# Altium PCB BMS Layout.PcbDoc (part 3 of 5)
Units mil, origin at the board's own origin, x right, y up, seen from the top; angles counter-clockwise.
Board outline 5576.78 x 4051.82 mil, 6 copper layers (Top Layer, GND1, Analog Signal, Power, GND2, Bottom Layer), stack 61.2 mil thick; 425 components, 206 nets, 1164 pads, 390 vias.
Unrouted connection lines stored in the file: 32.
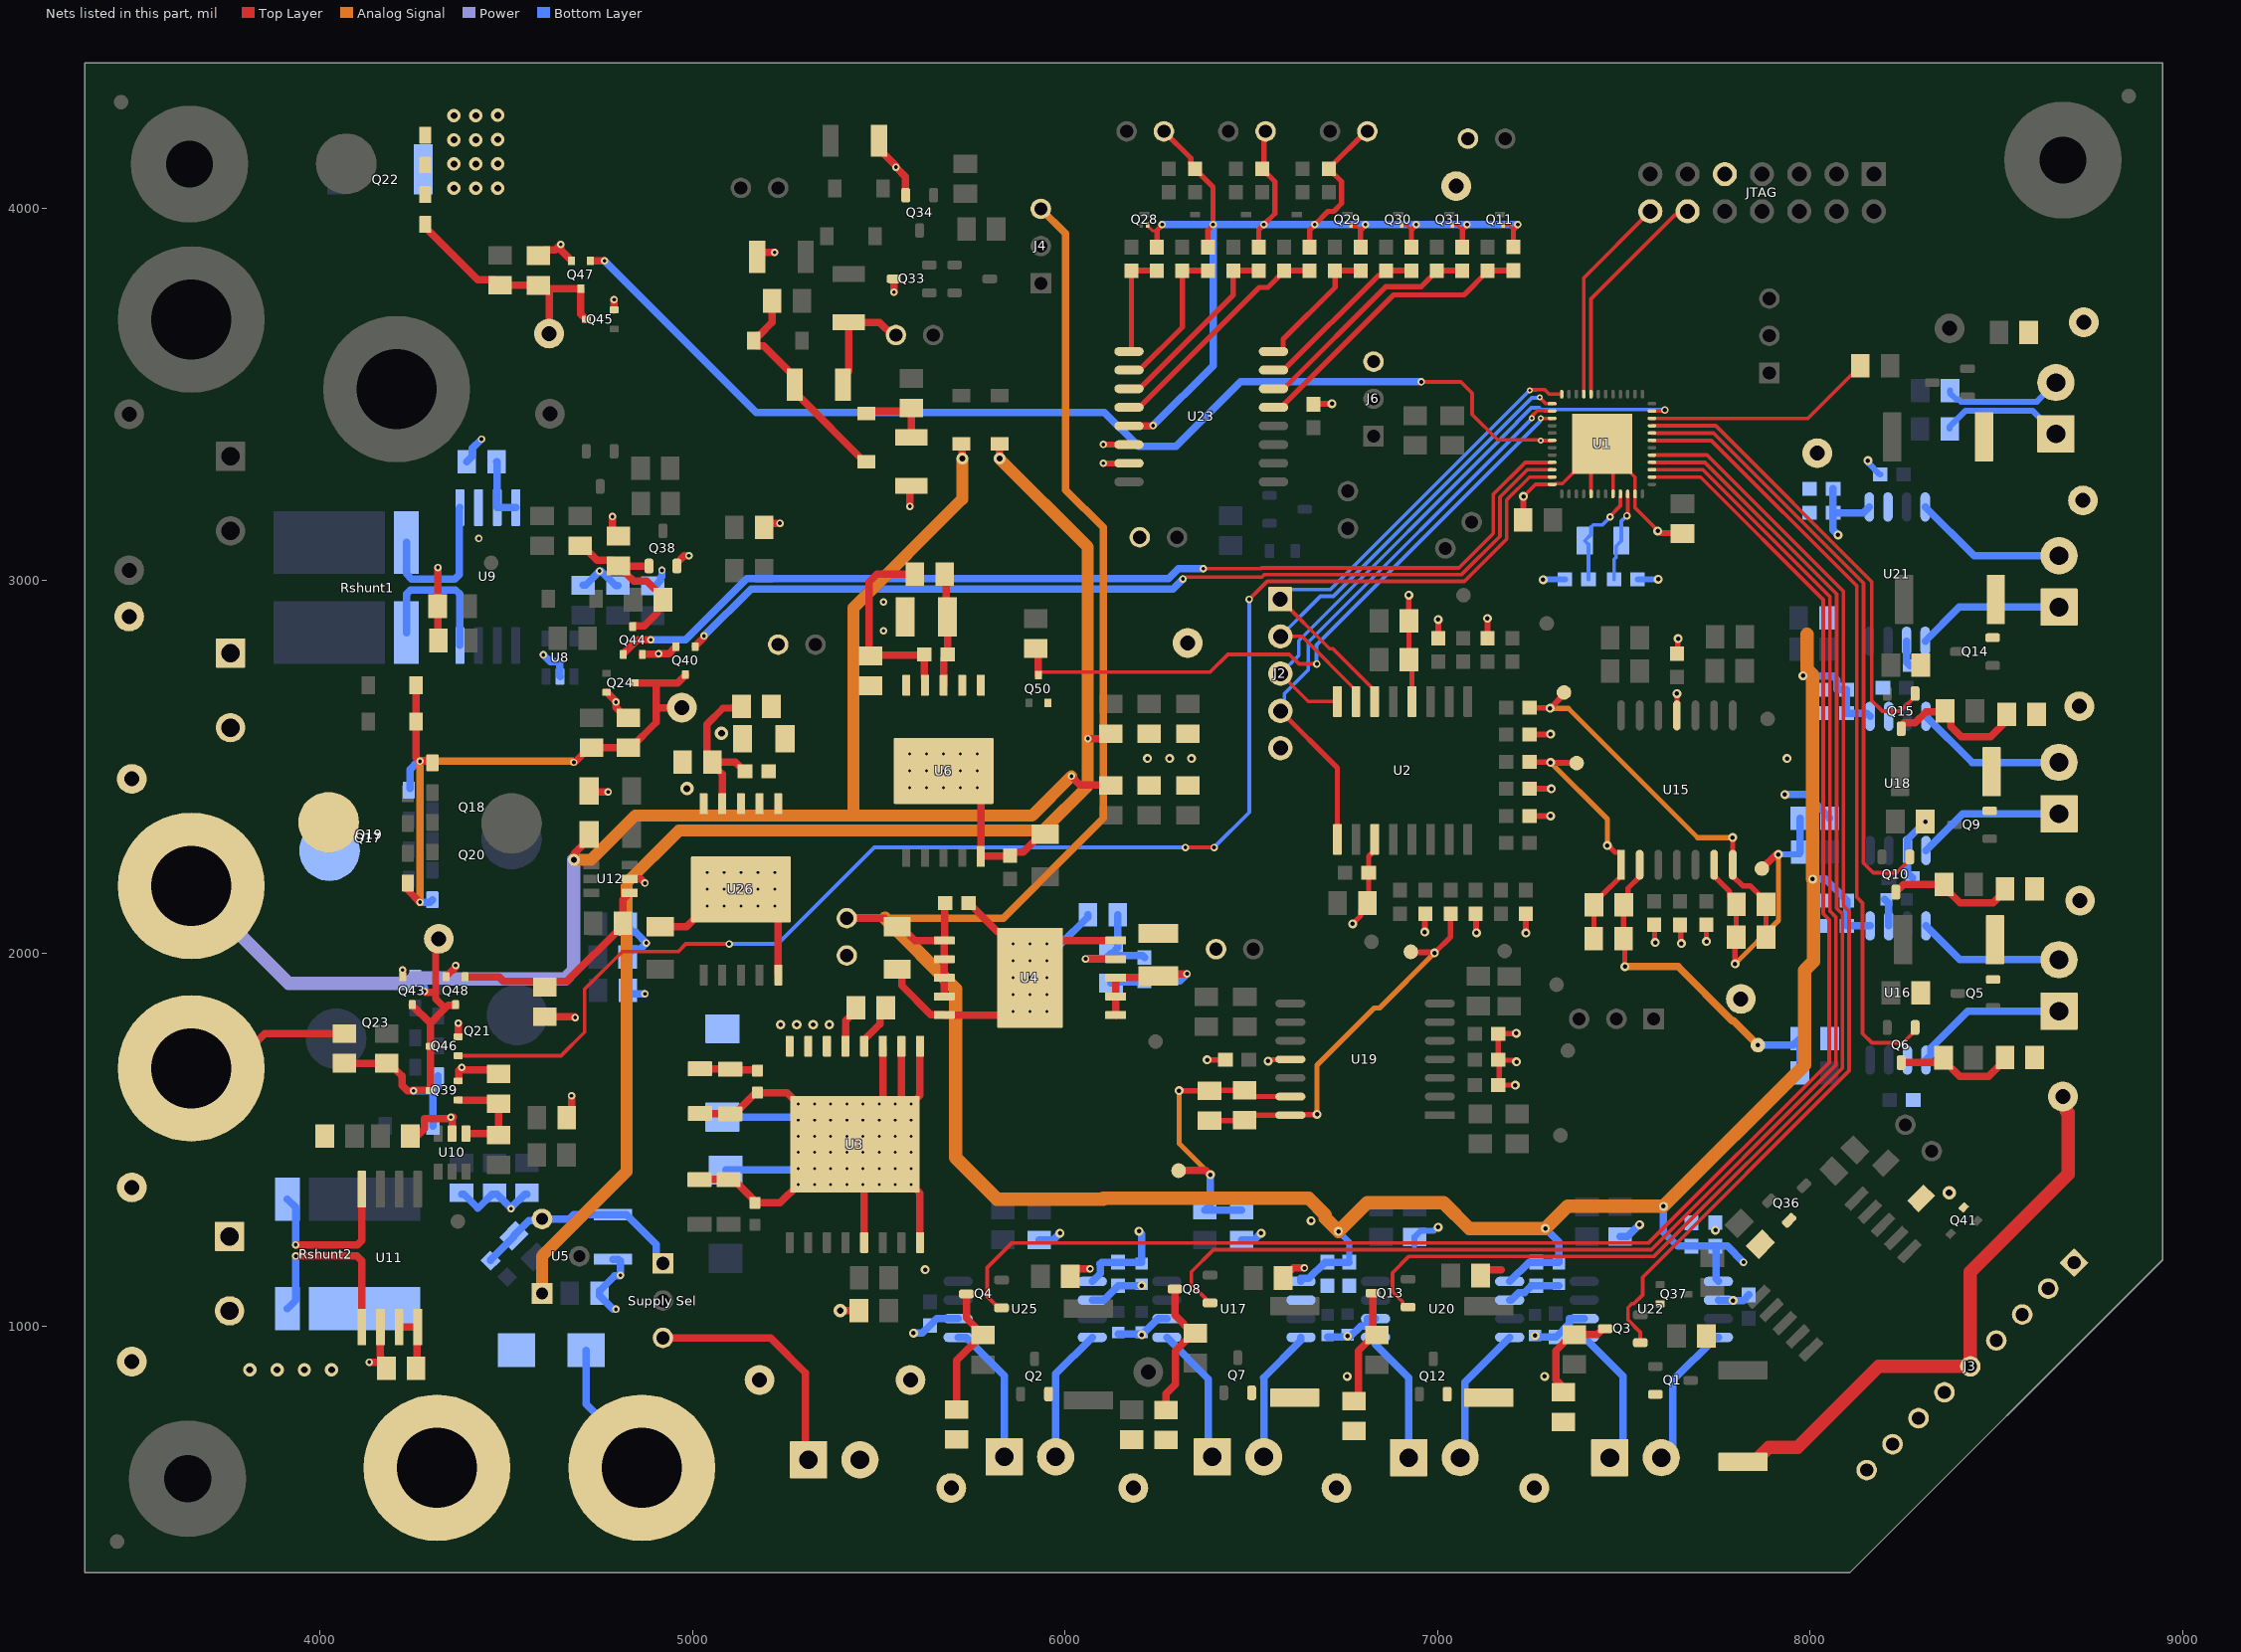
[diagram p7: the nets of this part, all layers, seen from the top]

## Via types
v1: diameter 20, hole 10, Top Layer to Bottom Layer, tented both sides, 113 vias
v2: diameter 24, hole 12, Top Layer to Bottom Layer, tented both sides, 103 vias
v3: diameter 19.68, hole 7.87, Top Layer to Bottom Layer, 93 vias
v4: diameter 36, hole 18, Top Layer to Bottom Layer, 46 vias
v5: diameter 36, hole 18, Top Layer to Bottom Layer, tented both sides, 12 vias
v6: diameter 16, hole 8, Top Layer to Bottom Layer, tented both sides, 10 vias
v7: diameter 26, hole 13, Top Layer to Bottom Layer, tented both sides, 7 vias
v8: diameter 32, hole 16, Top Layer to Bottom Layer, tented both sides, 3 vias
v9: diameter 28, hole 14, Top Layer to Bottom Layer, tented both sides, 2 vias
v10: diameter 20, hole 12, Top Layer to Bottom Layer, tented both sides, 1 vias

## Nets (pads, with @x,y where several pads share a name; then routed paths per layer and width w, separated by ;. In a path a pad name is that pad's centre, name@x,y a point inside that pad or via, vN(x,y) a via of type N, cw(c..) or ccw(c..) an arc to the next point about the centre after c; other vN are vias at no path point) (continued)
12Vcc: C16.1 C17.1 C87.2 C88.2 C90.2 C91.2 C95.2 C96.2 C99.2 C100.2 C104.2 C105.2 C109.2 C110.2 C153.2 C155.2 J4.3 J_LS.2 Q36.2 R139.2 U4.1 U4.2 U4.3 U4.4 U16.5 U17.5 U18.5 U20.5 U21.5 U22.5 U25.5 | length 9472.5
  Top Layer w20: J_LS.2@5414.11,2094.18 5515.48,2094.18 5538.48,2071.18 C16.1@5549.31,2071.18 5560.14,2071.18 5597.14,2034.18 U4.1@5675.81,2034.18 ; U4.4@5675.81,1884.18 U4.3@5675.81,1934.18 U4.2@5675.81,1984.18 U4.1@5675.81,2034.18 ; C17.1@5677.88,2134.77 5676.84,2133.73 5676.84,2035.01 5676.02,2034.18 U4.1@5675.81,2034.18
  Analog Signal w20: J_LS.2@5414.11,2094.18 5516.47,2094.18 5833.83,2094.18 6102.36,2362.71 6102.36,3142.77 6001.45,3243.68 6001.45,3931.74 J4.3@5935.04,3998.15
  Analog Signal w36: 5516.47,2094.18 5705.77,1904.88 5705.77,1451.83 5817.15,1340.44 6102.36,1340.44 ; 6102.36,1342.24 6653.77,1342.24 6698.5,1297.51 6698.5,1288.89 v2(6733.82,1253.57) 6811.35,1331.1 7015.12,1331.1 7085.04,1261.18 v2(7288.82,1261.18) 7348.76,1321.12 v2(7606.04,1321.12) 7984.64,1699.72 7984.64,1954.47 8008.54,1978.37 8008.54,2196.73 v2(8006.44,2198.83) 8006.44,2747.44 7991.01,2762.87 7991.01,2856.69
  Bottom Layer w16: v2(6733.82,1253.57) 6762.5,1224.88 C90.2@6762.5,1170.85
  Bottom Layer w20: U25.5@6073.05,1119.19 6095.26,1141.4 6095.26,1164.66 6093.68,1166.24 6098.29,1170.85 C153.2@6142.52,1170.85 6205.76,1170.85 6205.76,1246.96 v2(6198.39,1254.32) ; U17.5@6633.19,1119.19 6633.19,1127.26 6654.15,1127.26 6697.74,1170.85 C91.2@6704.63,1170.85 C90.2@6762.5,1170.85 ; U20.5@7193.33,1119.19 7244.8,1170.66 C100.2@7264.56,1170.66 7325.17,1170.66 7325.36,1170.85 7325.36,1224.64 v2(7288.82,1261.18) ; v2(7606.04,1321.12) 7606.04,1251.57 7643.86,1213.74 C110.2@7681.16,1213.74 7745.28,1213.74 C109.2@7745.47,1213.93 7778.06,1213.93 v1(7821.14,1170.85) ; C109.2@7746.92,1200.38 7746.92,1125.75 U22.5@7753.47,1119.19 ; v2(7980.3,2745.3) 7981.11,2744.49 8061.59,2744.49 8072.14,2733.95 8072.14,2708.64 8097.45,2708.64 C96.2@8097.45,2707.79 C95.2@8097.45,2644.58 8152.14,2644.58 U18.5@8160.57,2636.14 ; v2(8006.44,2198.83) 8041.27,2198.83 8097.92,2142.18 C88.2@8097.92,2141.33 8097.92,2073.83 8098.18,2073.57 U16.5@8160.57,2073.57 ; C105.2@8061.41,3247.28 C104.2@8061.41,3182.18 ; v2(8074.57,3123.03) 8061.41,3136.19 C104.2@8061.41,3182.18 ; U21.5@8158.53,3198 8142.71,3182.18 C104.2@8061.41,3182.18
A1_RX: JTAG.14 U1.21 | length 558
  Top Layer w10: U1.21@7391.9,3507.52 7391.9,3812.86 JTAG.14@7570.58,3991.54
A1_TX: JTAG.12 U1.20 | length 612.4
  Top Layer w10: U1.20@7411.59,3500.71 7411.59,3532.02 7411.5,3532.11 7411.5,3756.81 7635.72,3981.02 7660.06,3981.02 JTAG.12@7670.58,3991.54
ADC_CS: J2.4 U1.26 U2.1 | length 1539.8
  Top Layer w10: v6(7252.8,3436.03) 7253.95,3437.18 7253.95,3442.59 7268.1,3456.75 7285.5,3456.75 7286.54,3455.71 7306.98,3455.71 U1.26@7307.26,3455.43
  Top Layer w14: J2.4@6577.98,2650.6 6730.9,2497.69 U2.1@6730.9,2305.8
  Bottom Layer w10: J2.4@6577.98,2650.6 6588.5,2661.12 6588.5,2696.8 6652.71,2761.01 6652.71,2834.96 7252.8,3435.06 v6(7252.8,3436.03)
ADC_DIN: J2.1 U1.24 U2.14 | length 1378.9
  Top Layer w10: J2.1@6576.98,2950.6 6709.92,2817.67 6718.64,2817.67 6830.9,2705.41 U2.14@6830.9,2675.88 ; v6(7246.73,3510.92) 7247.87,3512.06 7264.35,3512.06 7265.09,3512.8 7287.38,3512.8 7299.47,3500.71 U1.24@7332.85,3500.71
  Bottom Layer w10: J2.1@6576.98,2950.6 6602.52,2976.14 6712.27,2976.14 7246.73,3510.59 v6(7246.73,3510.92)
ADC_DOUT: J2.2 U1.25 U2.15 | length 1294.4
  Top Layer w10: J2.2@6577.98,2850.6 6635.7,2850.6 6780.9,2705.41 U2.15@6780.9,2675.88 ; v6(7273.79,3491.8) 7290.2,3475.39 7306.98,3475.39 U1.25@7307.26,3475.12
  Bottom Layer w10: J2.2@6577.98,2850.6 6685.52,2958.14 6719.73,2958.14 7252.25,3490.66 7272.64,3490.66 v6(7273.79,3491.8)
ADC_SCLK: J2.3 U1.11 U2.16 | length 1573.4
  Top Layer w10: J2.3@6577.98,2750.6 6652.71,2675.88 U2.16@6730.9,2675.88 ; U1.11@7574.97,3455.43 7603.83,3455.43 7607.14,3458.75 v10(7609.85,3458.75)
  Bottom Layer w10: J2.3@6577.98,2750.6 6627.2,2799.82 6627.2,2838.9 7212.37,3424.07 7212.37,3425.29 7251.18,3464.11 7272.63,3464.11 7277.49,3459.25 7582.93,3459.25 7583.44,3458.75 v10(7609.85,3458.75)
BAL1_MCU: R75.2 U1.10 | length 618.2
  Top Layer w10: U1.10@7574.97,3435.75 7993.19,3435.75 R75.2@8134.59,3577.15
BAL2_MCU: Q15.1 U1.9 | length 1234.9
  Top Layer w10: U1.9@7574.97,3416.06 7746.15,3416.06 8164.96,2997.25 8164.96,2678.26 8193.42,2649.8 8242.05,2649.8 8281.42,2689.16 Q15.1@8281.42,2697.03
BAL3_MCU: Q10.1 U1.8 | length 1643.3
  Top Layer w10: U1.8@7574.97,3396.38 7740.38,3396.38 8142.89,2993.87 8142.89,2601.96 8142.7,2601.77 8142.7,2569.66 8142.89,2569.48 8142.89,2242.08 8168.77,2216.19 8231.96,2216.19 8266.97,2251.2 Q10.1@8266.97,2258.58
BAL4_MCU: Q6.1 U1.7 | length 2093.6
  Top Layer w10: U1.7@7574.97,3376.69 7575.25,3376.41 7734.88,3376.41 8124.7,2986.59 8124.7,2150.41 8140.57,2134.54 8140.57,1784.45 8165.55,1759.46 8249.02,1759.46 8274.61,1785.05 8274.61,1785.61 8281.42,1792.42 Q6.1@8281.42,1800.78
BAL5_MCU: Q3.1 U1.5 | length 2951.1
  Top Layer w10: Q3.1@7543.79,954.71 7543.79,983.09 7511.11,1015.78 7511.11,1049.11 7521.32,1059.32 7526.44,1059.32 7550.17,1083.04 7550.17,1130.4 8104.57,1684.8 8104.57,2112.52 8088.7,2128.38 8088.7,2971.68 7723.07,3337.32 U1.5@7574.97,3337.32
BAL6_MCU: Q13.1 U1.4 | length 3469.6
  Top Layer w10: Q13.1@6920.58,1050.29 6913.2,1050.29 6906.45,1057.03 6906.45,1064.42 6879.07,1091.8 6879.07,1142.4 6923.31,1186.65 7580.96,1186.65 8086.57,1692.26 8086.57,2105.06 8070.7,2120.93 8070.7,2964.23 7717.29,3317.64 U1.4@7574.97,3317.64
BAL7_MCU: Q8.1 U1.3 | length 3946.5
  Top Layer w10: Q8.1@6389.05,1061.45 6338.86,1111.63 6338.86,1144.98 6398.53,1204.65 7573.5,1204.65 8068.57,1699.71 8068.57,2097.61 8052.7,2113.47 8052.7,2956.77 7711.52,3297.95 U1.3@7574.97,3297.95
BAL8_MCU: Q4.1 U1.2 | length 4460.7
  Top Layer w10: Q4.1@5829.51,1048.31 5821.63,1048.31 5791.21,1078.73 5791.21,1156.35 5857.5,1222.65 7566.05,1222.65 8050.57,1707.17 8050.57,2090.15 8034.7,2106.01 8034.7,2949.31 7705.75,3278.27 U1.2@7574.97,3278.27
Batt1_4V2: Batt_1.1 Batt_2.2 J3.2 R40.1 R43.2 R106.1 TP39.1 U21.8 | length 748.8
  Bottom Layer w16: R106.1@8374.23,3407.51 8374.23,3414.01 8417.04,3456.82 8596.45,3456.82 Batt_1.1@8659.37,3393.9
  Bottom Layer w20: U21.8@8308.53,3198 8439.43,3067.11 Batt_2.2@8667.67,3067.11
Batt2_8V4: Batt_2.1 Batt_3.2 J3.3 Q14.2 R36.1 R37.1 TP38.1 U18.8 U21.1 | length 811
  Bottom Layer w20: U21.1@8308.53,2837.77 8399.87,2929.11 Batt_2.1@8667.67,2929.11 ; U18.8@8310.57,2636.14 8434.25,2512.46 Batt_3.2@8673.38,2512.46
Batt3_12V6: Batt_3.1 Batt_4.2 J3.4 Q9.2 R30.1 R32.1 TP37.1 U16.8 U18.1 | length 798.4
  Bottom Layer w20: U16.8@8310.57,2073.57 8401.5,1982.64 Batt_4.2@8667.67,1982.64 ; U18.1@8310.57,2275.9 8409.13,2374.46 Batt_3.1@8673.38,2374.46
Batt4_16V8: Batt_4.1 Batt_5.2 J3.5 Q5.2 R24.1 R26.1 TP36.1 U16.1 U22.8 | length 2380.4
  Top Layer w36: R26.1@7819.44,634.7 7860.78,634.7 7867.39,641.31 7867.39,652.44 7888.48,673.52 7965.95,673.52 8183.56,891.14 J3.5@8429.76,891.14 8429.76,1144.98 8691.69,1406.9 8691.69,1572.5 8686.39,1577.79 8686.39,1607.17 TP36.1@8677.97,1615.58
  Bottom Layer w20: Batt_5.2@7600.08,640.35 7631.56,671.83 7631.56,853.42 7747.33,969.19 U22.8@7753.47,969.19 ; U16.1@8310.57,1713.33 8323.92,1726.68 8323.92,1745.98 8422.58,1844.64 Batt_4.1@8667.67,1844.64
Batt5_21V: Batt_5.1 Batt_6.2 J3.6 Q1.2 R7.1 R33.1 TP33.1 U20.8 U22.1 | length 765.2
  Bottom Layer w20: Batt_6.2@7060.45,646.06 7060.45,677.8 7072.89,690.24 7072.89,848.75 U20.8@7193.33,969.19 ; U22.1@7393.24,969.19 7497.85,864.57 7497.85,676.12 Batt_5.1@7462.08,640.35
Batt6_25V2: Batt_6.1 Batt_7.2 J3.7 Q12.2 R27.1 R34.1 TP35.1 U17.8 U20.1 | length 723.2
  Bottom Layer w20: Batt_7.2@6533.17,648.22 6533.17,859.17 6532.33,860.01 6633.19,960.87 U17.8@6633.19,969.19 ; U20.1@6833.1,969.19 6833.1,950.18 6922.45,860.83 Batt_6.1@6922.45,646.06
Batt7_29V4: Batt_7.1 Batt_8.2 J3.8 Q7.2 R28.1 R66.2 TP34.1 U17.1 U25.8 | length 733.3
  Bottom Layer w20: Batt_8.2@5974.73,648.22 5974.73,870.86 U25.8@6073.05,969.19 ; U17.1@6272.96,969.19 6384.97,857.18 6384.97,658.42 Batt_7.1@6395.17,648.22
Batt_out: Batt.1 Batt_8.1 Batt_.1 C24.1 D1.2 J3.9 Q2.2 R9.1 R124.2 Rshunt2.2 TP16.1 TP24.1 U5.1 U25.1 | length 4009.9
  Top Layer w20: v8(5824.02,3327.55) D1.2@5824.02,3368.01 ; v1(6061.04,2576.23) 6109.46,2576.23 R124.2@6122.28,2589.04
  Analog Signal w32: U5.1@4596.26,1086.85 4596.26,1187.2 4823.02,1413.95 4823.02,2188.79 4963.73,2329.5 5941.39,2329.5 6061.04,2449.15 v1(6061.04,2576.23) 6061.04,3090.53 v8(5824.02,3327.55)
  Bottom Layer w20: U25.1@5712.82,969.19 5733.9,969.19 5836.73,866.36 Batt_8.1@5836.73,648.22
  other v4: 3811.54,881.88 3884.9,881.88 3958.26,881.88 4031.62,881.88
BattCurr+: Rshunt2.3 U11.8 | length 451.5
  Top Layer w20: v1(3934.75,1217.5) 4100.71,1217.5 4112.43,1229.22 U11.8@4112.43,1366.74
  Bottom Layer w20: Rshunt2.3@3912.8,1339.86 3934.75,1317.91 v1(3934.75,1217.5)
BattCurr-: Rshunt2.4 U11.1 | length 510.6
  Top Layer w20: v1(3935.5,1187.24) 4099.27,1187.24 4112.43,1174.08 U11.1@4112.43,996.66
  Bottom Layer w20: Rshunt2.4@3912.8,1045.86 3935.5,1068.56 v1(3935.5,1187.24)
Charger_Vin: Charger.2 Charger_.1 D2.2 Q17.5 Q19.5 R55.2 R140.2 TP22.1 | length 4197.3
  Top Layer w20: v8(4681.42,2251.33) 4683.72,2253.62 4683.72,2269.07 4722.62,2307.97 R55.2@4722.62,2318.8 ; D2.2@5721.53,3368.01 5723.86,3365.67 v8(5723.86,3327.55) ; v1(6017.24,2475.41) 6040.43,2452.22 6120.28,2452.22 R140.2@6122.28,2450.23
  Analog Signal w32: v8(4681.42,2251.33) 4728.43,2251.33 4846.6,2369.5 5432.27,2369.5 ; v8(5723.86,3327.55) 5723.86,3219.26 5432.27,2927.67 5432.27,2369.5 ; v1(6017.24,2475.41) 5911.33,2369.5 5432.27,2369.5
  Power w36: Charger_.1@3654.53,2180.81 3915.96,1919.38 4237.01,1919.38 4251.44,1933.81 4346.77,1933.81 4349.34,1931.24 4657.76,1931.24 4681.42,1954.9 v8(4681.42,2251.33)
D1: C118.1 R112.2 U23.4 | length 637.3
  Top Layer w14: U23.4@6171.58,3465.3 6174.72,3468.45 6202.28,3468.45 6521.39,3787.55 6544.33,3787.55 6588,3831.23 R112.2@6588,3832.21
  Top Layer w16: R112.2@6588,3832.21 C118.1@6656.37,3832.21
D2: C115.1 R113.2 U23.3 | length 517.3
  Top Layer w14: U23.3@6171.58,3515.3 6199.14,3515.3 6451.38,3767.55 R113.2@6451.38,3832.21
  Top Layer w16: R113.2@6451.38,3832.21 C115.1@6519.76,3832.21
D3: C119.1 R114.2 U23.2 | length 410.7
  Top Layer w14: U23.2@6171.58,3565.3 6199.14,3565.3 6314.77,3680.94 R114.2@6314.77,3832.21
  Top Layer w16: R114.2@6314.77,3832.21 C119.1@6383.14,3832.21
D4: C116.1 R115.2 U23.1 | length 289.2
  Top Layer w14: U23.1@6171.58,3615.3 6173.71,3615.3 6178.16,3619.75 R115.2@6178.16,3832.21
  Top Layer w16: R115.2@6178.16,3832.21 C116.1@6246.53,3832.21
D5: C120.1 R116.2 U23.16 | length 366.2
  Top Layer w14: U23.16@6559.38,3615.3 6580.73,3615.3 6585.17,3619.75 6585.17,3648.12 6724.61,3787.55 R116.2@6724.61,3832.21
  Top Layer w16: R116.2@6724.61,3832.21 C120.1@6792.98,3832.21
D6: C117.1 R117.2 U23.15 | length 481.4
  Top Layer w14: U23.15@6559.38,3565.3 6586.94,3565.3 6841.15,3819.52 6849.52,3819.52 6861.22,3831.23 R117.2@6861.22,3832.21
  Top Layer w16: R117.2@6861.22,3832.21 C117.1@6929.6,3832.21
D7: C121.1 R118.2 U23.14 | length 638.7
  Top Layer w14: U23.14@6559.38,3515.3 6562.52,3518.45 6590.08,3518.45 6861.18,3789.55 6956.16,3789.55 6997.84,3831.23 R118.2@6997.84,3832.21
  Top Layer w16: R118.2@6997.84,3832.21 C121.1@7066.21,3832.21
D8: C156.1 R6.2 U23.13 | length 799.3
  Top Layer w14: U23.13@6559.38,3465.3 6584.33,3465.3 6588.78,3469.75 6588.78,3474.92 6881.4,3767.55 7070.7,3767.55 7134.38,3831.23 R6.2@7134.38,3832.21
  Top Layer w16: R6.2@7134.38,3832.21 7134.64,3832.47 7202.66,3832.47 C156.1@7202.92,3832.73
D-: C115.2 C116.2 C117.2 C118.2 C119.2 C120.2 C121.2 C156.2 Q11.2 Q28.2 Q29.2 Q30.2 Q31.2 R129.2 R131.2 R133.2 Sensor1.1 Sensor2.1 Sensor3.1 U23.5 | length 3250.1
  Top Layer w8: Q28.2@6221.68,3955.14 6221.68,3952.19 6233.89,3939.97 6246.53,3939.97 ; Q29.2@6767.04,3955.14 6767.04,3952.19 6767.96,3951.27 6782.78,3951.27 6792.98,3941.06 ; Q30.2@6903.38,3955.14 6915.79,3955.14 6929.6,3941.34 ; Q31.2@7039.72,3955.14 7052.68,3955.14 7066.21,3941.61 ; Q11.2@7176.06,3955.14 7189.75,3955.14 7202.92,3941.97
  Top Layer w14: C116.2@6246.53,3895.2 6246.53,3939.97 6260.77,3954.21 v1(6260.77,3955.83) ; Sensor3.1@6265.18,4206.2 6337.46,4133.92 6337.46,4117.53 R133.2@6349.16,4105.83 6349.16,4104.85 6397.11,4056.9 v1(6397.11,3955.83) 6397.11,3954.21 6383.14,3940.24 C119.2@6383.14,3895.2 ; C115.2@6519.76,3895.2 6519.76,3942.14 v1(6533.45,3955.83) 6563.04,3985.42 6563.04,4071.15 6529.34,4104.85 R131.2@6529.34,4105.83 6533.76,4110.25 6533.76,4201.78 Sensor2.1@6538.17,4206.2 ; C118.2@6656.37,3895.2 6656.37,3940.79 6669.79,3954.21 v1(6669.79,3955.83) 6705.77,3991.81 6721.32,3991.81 6742.06,4012.55 6742.06,4071.15 6708.36,4104.85 R129.2@6708.36,4105.83 6708.36,4106.82 6807.74,4206.2 Sensor1.1@6811.17,4206.2 ; C120.2@6792.98,3895.2 6792.98,3941.06 6806.13,3954.21 v1(6806.13,3955.83) ; C117.2@6929.6,3895.2 6929.6,3941.34 6942.47,3954.21 v1(6942.47,3955.83) ; C121.2@7066.21,3895.2 7066.21,3941.61 7078.81,3954.21 v1(7078.81,3955.83) ; C156.2@7202.92,3895.72 7202.92,3941.97 7215.15,3954.21 v1(7215.15,3955.83)
  Top Layer w20: U23.5@6171.58,3415.3 6234.9,3415.3 v1(6235.85,3416.25)
  Bottom Layer w20: v1(6235.85,3416.25) 6236.24,3416.25 6397.11,3577.12 v1(6397.11,3955.83) ; v1(6260.77,3955.83) v1(6397.11,3955.83) ; v1(7215.15,3955.83) v1(7078.81,3955.83) v1(6942.47,3955.83) v1(6806.13,3955.83) v1(6669.79,3955.83) v1(6533.45,3955.83) v1(6397.11,3955.83)
"FlipFlop GPIO4": Q44.1 U1.33 | length 2766.6
  Top Layer w10: v1(6370.95,3032.73) 6526,3032.73 6527.96,3034.69 7057,3034.69 7094.92,3072.61 7149.2,3126.89 7149.2,3231.83 7235.01,3317.64 U1.33@7307.26,3317.64
  Top Layer w20: Q44.1@4814.91,2804.02 4852.42,2841.53 v1(4887.87,2841.53)
  Bottom Layer w20: v1(4887.87,2841.53) 4980.99,2841.53 5145.5,3006.04 6277.66,3006.04 6304.36,3032.73 v1(6370.95,3032.73)
G1: C30.1 D4.1 D5.1 Q17.1 Q18.1 Q19.1 Q20.1 Q24.3 Q40.3 R42.2 TP31.1 | length 1800.5
  Top Layer w20: Q17.1@4235.89,2188.72 4235.89,2169.5 v1(4268.28,2137.11) ; D5.1@4258.57,2719.91 D4.1@4258.57,2622.2 4258.57,2525.03 v1(4268.28,2515.32) 4284.86,2515.32 4288.64,2519.1 Q18.1@4288.64,2519.74 ; v1(4681.51,2512.49) 4683.2,2512.49 4722.76,2552.04 R42.2@4729.26,2552.04 4834.74,2552.04 4902.02,2619.32 4902.02,2658.21 ; Q24.3@4843.83,2725.82 4902.02,2725.82 ; TP31.1@4971.28,2659.55 4969.94,2658.21 4902.02,2658.21 ; Q40.3@4981.28,2747.97 4981.28,2746.91 4960.2,2725.82 4902.02,2725.82 ; 4902.02,2658.21 4902.02,2725.82
  Analog Signal w20: v1(4268.28,2137.11) v1(4268.28,2515.32) 4678.68,2515.32 v1(4681.51,2512.49)
  Bottom Layer w20: Q19.1@4241.83,2441.99 4241.83,2493.65 4263.5,2515.32 v1(4268.28,2515.32) ; v1(4268.28,2137.11) 4295.58,2137.11 Q20.1@4301.96,2143.49
G1_on_off: Q40.1 U1.34 | length 2561.6
  Top Layer w10: v1(6316.57,3004.73) 6319.28,3004.73 6324.28,3009.73 6528.46,3009.73 6535.41,3016.69 7064.45,3016.69 7167.2,3119.44 7167.2,3224.37 7240.78,3297.95 U1.34@7307.26,3297.95
  Top Layer w20: Q40.1@5006.88,2822.77 5006.88,2823.83 5030.82,2847.78 v1(5030.82,2851.77)
  Bottom Layer w20: v1(5030.82,2851.77) 5157.1,2978.04 6289.88,2978.04 v1(6316.57,3004.73)
G2: C32.1 D6.1 Q21.1 Q23.1 Q39.3 Q43.3 Q46.3 Q48.3 R41.2 TP19.1 | length 1094.5
  Top Layer w20: C32.1@4065.85,1704.68 R41.2@4179.67,1704.68 4186.17,1704.68 4220.61,1670.24 4220.61,1645.15 4234.75,1631.01 v1(4251.48,1631.01) ; v1@4247.3,1631.84 Q39.3@4296.26,1631.84 4296.26,1792.9 4296.26,1812.33 ; Q43.3@4247.69,1861.96 4247.69,1860.9 4296.26,1812.33 ; v1(4280.65,1897.81) 4282.71,1895.75 4310.66,1895.75 ; TP19.1@4319.28,2039.11 4310.66,2030.49 4310.66,1895.75 ; Q48.3@4364.25,1861.96 4364.25,1860.9 4363.5,1860.15 4344.08,1860.15 4336.02,1852.09 ; 4296.26,1812.33 4336.02,1852.09 ; 4310.66,1895.75 4310.66,1877.44 4336.02,1852.09
  Bottom Layer w20: v1(4251.48,1631.01) 4300.35,1631.01 4304.13,1627.23 ; Q23.1@4257.1,1940.46 4260.88,1936.68 4260.88,1928.81 4280.65,1909.04 v1(4280.65,1897.81) ; D6.1@4303.71,1536.45 4303.92,1536.66 4303.92,1621.28 ; 4304.13,1624.86 4304.13,1627.23 ; Q21.1@4316.88,1671.32 4316.88,1639.98 4304.13,1627.23
G2_on_off: Q46.1 U1.35 | length 4044.2
  Top Layer w10: Q46.1@4371.06,1724.99 4647.02,1724.99 4710.62,1788.6 4710.62,1903.62 4811.73,2004.73 4961.74,2004.73 4982.14,2025.13 v1(5098.26,2025.13) ; v1@6323.34,2283.49 v1(6322.69,2284.15) v1(6400,2284.15) ; v1(6494.36,2950.18) 6542.87,2998.69 7071.91,2998.69 7185.2,3111.98 7185.2,3216.92 7246.55,3278.27 U1.35@7307.26,3278.27
  Bottom Layer w10: v1(5098.26,2025.13) 5228.74,2025.13 5487.76,2284.15 v1(6322.69,2284.15) ; v1(6400,2284.15) 6494.36,2378.51 v1(6494.36,2950.18)
G3: C31.1 Q22.1 Q45.3 Q47.3 R45.1 TP21.1 | length 708.2
  Top Layer w20: Q22.1@4283.46,3956.06 4283.46,3948.19 4423.86,3807.79 4468.88,3807.79 4483.88,3792.79 C31.1@4586.61,3792.79 4593.11,3792.79 C31.1@4601.86,3784.05 ; TP21.1@4615.16,3663.46 4615.16,3770.75 C31.1@4601.86,3784.05 ; Q45.3@4714.75,3701.3 4713.69,3701.3 4712.94,3702.05 4712.94,3703.11 4700.34,3715.71 Q47.3@4700.34,3784.05 C31.1@4601.86,3784.05
G3_on_off: Q47.1 U1.30 | length 2958.2
  Top Layer w10: v1(6956.16,3533.81) 7062.63,3533.81 7092.67,3503.77 7092.67,3446.46 7161.13,3378.01 v6@7276.13,3378.01 ; v6(7276.13,3375.75) 7276.8,3376.41 7306.98,3376.41 U1.30@7307.26,3376.69
  Top Layer w20: Q47.1@4725.93,3858.85 v1(4763.78,3858.85)
  Bottom Layer w20: v1(4763.78,3858.85) 5170.71,3451.92 6105.76,3451.92 6197.43,3360.25 6297.02,3360.25 6470.58,3533.81 v1(6956.16,3533.81)
Gate2: Q15.3 R36.2 R72.2 | length 385.7
  Top Layer w20: Q15.3@8244,2602.56 8244,2610.4 8252.31,2618.72 8281.66,2618.72 8310.3,2647.36 8346.8,2647.36 8346.8,2639.14 8351.62,2634.32 8371.98,2634.32 8376.8,2629.49 8376.8,2609.14 8404.89,2581.05 8484.42,2581.05 8527.47,2624.09 R36.2@8527.47,2641.19
Gate3: Q10.3 R30.2 R68.2 | length 349.8
  Top Layer w20: Q10.3@8229.57,2164.09 8229.57,2171.97 8231.38,2173.78 8239.25,2173.78 8250.16,2184.68 R68.2@8358.93,2184.68 8358.93,2178.18 8401.93,2135.18 8491.11,2135.18 8522.42,2166.5 R30.2@8522.42,2173
Gate4: Q6.3 R24.2 R64.2 | length 332.7
  Top Layer w20: Q6.3@8244.02,1706.3 8344.75,1706.3 R64.2@8357.92,1719.46 8357.92,1712.96 8400.92,1669.96 8478.98,1669.96 8522.42,1713.41 R24.2@8522.42,1719.91
Gate5: Q3.3 R7.2 R60.2 | length 277.9
  Top Layer w20: R7.2@7337.61,821.68 7337.61,835.24 7317.17,855.68 7317.17,933.36 7360.17,976.36 R60.2@7366.67,976.36 7427.91,976.36 7439.62,988.08 7439.62,990.3 7441.43,992.11 Q3.3@7449.31,992.11
Gate6: Q13.3 R34.2 R70.2 | length 323.1
  Top Layer w20: R34.2@6775.32,797.93 6786.85,809.46 6786.85,932.51 6829.85,975.51 R70.2@6836.35,975.51 6826.09,985.76 Q13.3@6826.09,1087.69
Gate7: Q8.3 R28.2 R65.2 | length 381.3
  Top Layer w20: R28.2@6270.76,773.87 6270.76,817.47 6296.12,842.83 6296.12,933.23 R65.2@6342.86,979.97 ; Q8.3@6294.56,1098.85 6294.56,1028.27 R65.2@6342.86,979.97 ; R65.2@6349.36,979.97 R65.2@6342.86,979.97
Gate8: Q4.3 R9.2 R61.2 | length 359.2
  Top Layer w20: R9.2@5709.21,775.4 5709.21,906.96 5777.75,975.51 R61.2@5779.71,975.51 5735.02,1020.2 Q4.3@5735.02,1085.71
GND: "12V Supply.2" Batt.2 Batt_1.2 C1.2 C2.2 C3.2 C4.2 C5.2 C6.2 C7.2 C8.2 C10.1 C12.1 C13.1 C14.1 C16.2 C17.2 C18.1 C19.2 C20.1 C21.1 C22.1 C23.1 C24.2 C26.2 C27.2 C28.2 C30.2 C31.2 C32.2 C34.2 C35.2 C36.2 C37.2 C38.2 C39.2 C40.2 C41.2 C42.2 C43.2 C44.2 C45.2 C46.2 C47.2 C48.2 C49.2 C51.2 C52.2 C53.2 C79.2 C86.2 C87.1 C88.1 C89.2 C90.1 C91.1 C94.2 C95.1 C96.1 C98.2 C99.1 C100.1 C103.2 C104.1 C105.1 C107.2 C108.2 C109.1 C110.1 C111.2 C112.2 C114.1 C122.2 C123.2 C124.2 C126.2 C128.2 C133.1 C134.2 C135.2 C136.2 C137.2 C138.2 C139.1 C140.1 C141.1 C142.1 C143.1 C144.1 C145.1 C146.1 C147.1 C148.1 C149.1 C150.1 C151.2 C152.2 C153.1 C154.2 C155.1 C160.1 Charger.1 GND.1 GND_.1 J2.5 J3.1 J6.3 J_heater.2 JTAG.9 Q22.2 Q22.3 Q22.4 Q24.2 Q33.3 Q34.2 Q37.2 Q38.2 Q39.2 Q40.2 Q41.2 Q43.2 Q44.2 Q45.2 Q46.2 Q47.2 Q48.2 Q50.2 R5.1 R14.1 R15.1 R16.1 R17.1 R19.1 R23.1 R25.1 R29.1 R31.1 R35.1 R38.1 R39.1 R44.1 R57.1 R58.1 R59.1 R67.2 R88.1 R92.1 R96.1 R100.1 R104.1 R108.1 R109.1 R141.1 R142.1 TP2.1 TP3.1 TP4.1 TP5.1 TP6.1 TP8.1 TP9.1 TP10.1 U1.36 U1.41 U1.44 U1.47 U1.49 U2.3 U2.12 U3.5 U3.8 U3.9 U3.10 U3.11 U3.17 U4.5 U4.10 U4.11@5905.73,1934.18 U6.5 U6.10 U6.11@5673.86,2489.56 U8.2 U9.2 U10.2 U11.2 U12.2 U15.11 U16.2 U16.6 U17.2 U17.6 U18.2 U18.6 U19.11 U20.2 U20.6 U21.2 U21.6 U22.2 U22.6 U23.6 U23.7 U25.2 U25.6 U26.5 U26.10 U26.11@5129.91,2171.57 | length 12274.1
  Top Layer w10: v2(7230.12,3226.1) 7262.6,3258.58 U1.36@7307.26,3258.58 7313.79,3258.58 7315.75,3260.54 7334.81,3260.54 U1.49@7411.59,3337.32 ; U1.41@7411.59,3232.99 U1.49@7411.59,3337.32 ; U1.44@7470.64,3232.99 U1.49@7470.64,3337.32 ; v2(7590.45,3133.44) 7590.45,3135.33 7529.7,3196.09 U1.47@7529.7,3232.99 7529.7,3278.27 U1.49@7470.64,3337.32 ; U1.49@7411.59,3337.32 U1.49@7441.11,3366.85 U1.49@7470.64,3337.32
  Top Layer w14: v2(6381.41,1713.73) C139.1@6430.29,1713.73 ; v2(6544.85,1710.78) 6547.55,1710.78 6550.77,1713.99 6603.43,1713.99 U19.11@6604.71,1715.26 ; v2(6771.59,2078.75) 6793.41,2100.58 6793.41,2116.77 C6.2@6811.41,2134.77 6814.48,2137.84 C5.2@6814.48,2216.45 6814.48,2259.85 6830.9,2276.27 U2.3@6830.9,2305.8 ; v2(6922.43,2961.2) 6922.43,2892.1 C7.2@6922.73,2891.81 C8.2@6922.73,2788.32 6930.9,2780.15 U2.12@6930.9,2675.88 ; C154.2@7162.5,1713.73 C154.2@7162.98,1713.25 ; C154.2@7162.81,1714.05 C141.1@7162.81,1783.28 7163.76,1784.22 7210.08,1784.22 v2(7211.03,1785.17) ; C140.1@7175.18,1645.84 v2(7208.17,1645.84) ; C140.1@7175.18,1646.3 7162.96,1646.3 C140.1@7162.5,1646.77 7165.32,1649.58 7165.32,1711.9 7164.33,1711.9 C154.2@7162.98,1713.25 ; v2(7211.41,1708.41) 7208.7,1708.41 7203.87,1713.25 C154.2@7162.98,1713.25 ; C147.1@7581.12,2076.67 7582.44,2075.34 7582.44,2030.1 v2(7583.77,2028.77) ; U15.11@7642.08,2638.49 7642.2,2638.61 7642.2,2696.99 v2(7642.32,2697.11) ; C144.1@7642.08,2804.07 7644.47,2806.46 7644.47,2843.56 v2(7645.62,2844.7) ; C107.2@7650.35,2076.22 7652.47,2074.1 7652.47,2028.5 v2(7654.38,2026.59) ; C146.1@7721.11,2076.56 7721.4,2076.27 7721.4,2031.63 v2(7721.68,2031.34)
  Top Layer w16: v1(6102.36,3315.3) U23.7@6171.58,3315.3 ; v1(6102.37,3365.67) 6102.55,3365.49 6171.4,3365.49 U23.6@6171.58,3365.3 ; C114.1@6666.99,3473.55 6667.75,3474.31 6715.87,3474.31 v2(6716.63,3475.08) ; v2(6965.32,2056.77) 6966.15,2057.6 6966.15,2105.47 C86.2@6966.99,2106.31 ; v2(7001.62,2895.97) 7001.67,2895.92 C152.2@7001.72,2845.49 C152.2@7001.72,2845.49 ; C94.2@7102.11,2106.31 7102.99,2105.42 7102.99,2055.92 v2(7103.88,2055.03) ; v2(7133.77,2898.91) 7133.97,2898.72 7133.97,2845.68 C108.2@7134.17,2845.49 ; C2.2@7229.11,3163.03 7230.12,3164.03 v2(7230.12,3226.1) ; v2(7237.15,2054.25) v2(7237.15,2054.25) C103.2@7237.23,2106.31 C103.2@7237.23,2106.31 ; C111.2@7246.8,2368.79 v2(7302.86,2368.79) ; C89.2@7246.8,2441.46 v2(7304.83,2441.46) ; C98.2@7246.8,2586.81 7247.41,2587.41 7302.56,2587.41 v2(7303.16,2588.01) ; v2(7590.45,3133.44) 7592.61,3133.44 7598.57,3127.48 7656.07,3127.48 C1.2@7656.96,3126.58
  Top Layer w20: GND_.1@3654.53,1635.17 GND_.1@3729.01,1635.17 ; GND_.1@3729.01,1661.51 3852.18,1784.68 C32.2@4065.85,1784.68 ; v1(4132.73,902.45) C36.2@4163.22,902.45 ; U11.2@4162.43,996.66 4162.43,918.99 4163.22,918.19 C36.2@4163.22,902.45 ; C36.2@4178.22,885.77 4178.22,887.45 C36.2@4163.22,902.45 ; Q43.2@4222.1,1936.76 v1(4222.1,1955.38) ; C46.2@4260.61,1508.85 4280.89,1529.13 4280.89,1556.38 4341.2,1556.38 ; v1(4316.68,3035.63) 4316.68,2931.85 4317.01,2931.53 4317.01,2840.47 C41.2@4317.87,2839.61 ; Q48.2@4339.41,1938.57 4364.25,1963.42 v1(4364.25,1967.24) ; U10.2@4354.92,1518.02 4354.92,1556.41 v1@4358.21,1559.7 ; Q39.2@4371.06,1657.43 4372.13,1657.43 4372.87,1658.18 4372.87,1685.66 v1(4380.51,1693.3) 4386.89,1686.91 4468.06,1686.91 C52.2@4478.99,1675.98 ; Q46.2@4371.06,1776.17 v1(4371.06,1812.33) ; C31.2@4586.61,3872.79 4601.61,3887.79 4631.58,3887.79 v1(4646.38,3902.59) 4646.38,3888.29 4674.75,3859.92 Q47.2@4674.75,3858.85 ; C53.2@4604.15,1829.4 4683.24,1829.4 v1(4685,1827.64) ; R57.1@4662.26,1558.68 4675.3,1571.72 v1(4675.3,1617.71) ; R58.1@4722.62,2435.48 4725.33,2432.78 v1(4773.62,2432.78) ; Q24.2@4769.03,2700.23 4770.09,2700.23 4794.24,2676.08 v1(4794.24,2674.16) 4794.24,2659.55 4821.74,2632.04 C30.2@4828.24,2632.04 ; v1(4785.1,3172.18) 4785.1,3134.87 4800.1,3119.87 C51.2@4801.43,3119.87 ; Q45.2@4789.55,3726.89 v1(4789.55,3754.65) ; U12.2@4830.89,2199.3 4861.66,2199.3 v1(4872.61,2188.34) ; Q44.2@4865.34,2802.2 4907.13,2802.2 v1(4908.94,2804.02) 4936.94,2804.02 4953.88,2820.96 4954.95,2820.96 4955.69,2821.71 Q40.2@4955.69,2822.77 ; C34.2@4913.37,2071.18 4983.85,2071.18 5038.97,2126.3 v3(5039.36,2126.3) ; Q38.2@4958.06,3039.52 4958.06,3047.39 4977.56,3066.9 v1(4990.16,3066.9) ; C14.1@5018.97,1392.65 C22.1@5096.89,1392.65 5109.39,1392.65 5162.72,1339.32 5162.72,1334.97 C13.1@5167.48,1330.21 5235.39,1330.21 5284,1378.82 v3(5284.19,1378.82) ; C10.1@5019.89,1569.95 5020.42,1569.42 5100.58,1569.42 C20.1@5101.11,1568.89 5113.61,1568.89 C12.1@5164.85,1620.13 ; C124.2@5173.55,3869.28 5173.55,3869.63 5185.21,3881.28 v1(5220.25,3881.28) ; C12.1@5174.34,1625.88 5253.47,1625.88 5284,1595.35 v3(5284.19,1595.35) ; R59.1@5192,3143.62 5202.85,3154.46 v1(5234.6,3154.46) ; v3(5220.47,2126.3) 5229.91,2116.85 U26.5@5229.91,1941.65 ; v5(5396.7,1041.02) R15.1@5455.24,1041.02 ; v3(5457.42,1378.82) 5460.77,1375.47 U3.5@5460.77,1223.58 ; C126.2@5500.42,4181.06 5500.42,4159.4 5546.01,4113.81 v1(5546.01,4110.25) 5571.73,4084.54 5571.73,4035.25 Q34.2@5572.12,4034.85 ; v3(5500.73,1595.35) 5510.77,1605.39 U3.11@5510.77,1750.58 ; v1(5540.91,3774.63) Q33.3@5540.91,3810.22 ; v3(5544.04,1595.35) 5549.31,1595.35 5560.77,1606.81 U3.10@5560.77,1750.58 ; C16.2@5549.31,1957.01 5561.89,1944.43 5561.89,1913.13 5640.02,1835.01 5674.98,1835.01 U4.5@5675.81,1834.18 5851,1834.18 v3(5860.45,1843.63) ; v1(5583.31,3199.8) 5583.31,3251.07 C28.2@5586.93,3254.69 ; v3(5587.34,1378.82) 5587.54,1378.82 5610.77,1355.59 U3.8@5610.77,1223.58 ; v3(5587.34,1595.35) 5587.54,1595.35 5610.77,1618.58 U3.9@5610.77,1750.58 ; C17.2@5740.88,2134.77 5741.86,2134.77 5818.2,2058.43 5827.14,2058.43 5860.45,2025.13 v3(5860.45,2024.73) ; v3(5764.42,2444.29) 5773.86,2434.84 U6.5@5773.86,2260.14 ; U6.5@5773.86,2259.64 U6.5@5773.86,2260.14 ; C79.2@5946.62,2319.66 5935.79,2319.66 5888.1,2271.97 5860.54,2271.97 5851.84,2263.27 C26.2@5851.84,2262.29 5850.52,2260.97 5774.69,2260.97 U6.5@5773.86,2260.14 ; v3(5951,2024.73) 5960.45,2034.18 U4.10@6135.65,2034.18 ; R25.1@6013.68,1132.97 6013.68,1138.06 6028.68,1153.06 v1(6067.26,1153.06) ; R31.1@6585.13,1128.31 6585.13,1134.81 6600.13,1149.81 6606.63,1149.81 6612.08,1155.26 v1(6642.55,1155.26) ; R38.1@7115.32,1134.94 7115.32,1135.28 7130.32,1150.28 7170.11,1150.28
  Bottom Layer w16: R96.1@6937.83,1215.75 R96.1@6937.83,1238.43 6954.83,1255.43 6989.77,1255.43 6999.16,1264.82 v2(7001.32,1264.82) ; v2(7282.89,3003.01) 7283.09,3003.22 7341.33,3003.22 C3.2@7341.54,3003.42 ; C4.2@7536.53,3003.42 7536.78,3003.68 7591.82,3003.68 v2(7592.08,3003.93) ; v2(8154.95,3322.6) 8156.48,3321.07 8156.48,3315.15 8186.77,3284.86 C137.2@8187.75,3284.86 ; R108.1@8374.97,3510.51 8374.97,3504.01 8391.97,3487.01 8398.47,3487.01 8404.66,3480.82 8608.29,3480.82 Batt_1.2@8659.37,3531.9
  Bottom Layer w20: C43.2@4380.23,1353.36 4386.73,1353.36 4424.08,1316.01 4424.08,1315.13 4462.31,1353.36 4468.81,1353.36 4475.31,1353.36 v1@4512.96,1315.71 ; C35.2@4394.01,3319.65 4409.01,3334.65 4409.01,3355.36 v1(4433.77,3380.12) ; v1(4512.96,1314.41) v1@4512.96,1315.71 ; C44.2@4556.25,1353.36 4549.75,1353.36 4512.96,1316.57 v1@4512.96,1315.71 ; v1(4599.41,2800.84) 4617.99,2782.26 4643.23,2782.26 4643.23,2744.01 U8.2@4644.63,2742.6 ; C38.2@4706.31,2987.74 4712.81,2987.74 4750.75,3025.67 v1(4750.75,3026.13) 4754.9,3026.13 4793.9,2987.13 C37.2@4800.4,2987.13 ; C24.2@4714.86,934.53 4714.86,790.45 4863.79,641.52 GND.1@4863.79,618.56 ; C18.1@4786.35,1178.44 4801.82,1178.44 4806.58,1173.67 v1(4806.58,1135.44) 4804.82,1133.67 4790.46,1133.67 4750.38,1093.59 4750.38,1080.59 4786.53,1044.44 v1(4794.52,1044.44) ; C47.2@4826.09,1989.7 4826.09,1996.2 4841.09,2011.2 4859.66,2011.2 v1(4876.19,2027.73) 4847.9,2056.02 4841.09,2056.02 4826.09,2071.02 C48.2@4826.09,2077.52 ; C49.2@4826.27,1900.51 4835.99,1890.79 v1(4872.61,1890.79) ; C39.2@4893.6,2986.24 4900.1,2986.24 4915.1,3001.24 4915.1,3007.74 4918.01,3010.66 v1(4918.01,3027.94) ; C23.1@5080.44,1560.15 5276.09,1560.15 v3(5284.19,1552.04) ; C21.1@5088.88,1417.99 5280.06,1417.99 v3(5284.19,1422.12) ; v2(5592.83,980.48) 5616.94,980.48 C142.1@5637.48,1001.02 5655.65,1019.19 U25.2@5712.82,1019.19 ; R5.1@5930.29,1230.39 5967.67,1230.39 v2(5986.06,1248.78) ; v3(5951,2024.73) 5988.47,2024.73 6061.04,2097.3 R16.1@6061.04,2103.8 ; U25.6@6073.05,1069.19 6103.85,1069.19 C153.1@6142.52,1107.86 v2(6205.76,1107.86) ; C151.2@6142.86,978.14 6203.55,978.14 v2(6205.88,975.8) 6249.27,1019.19 U17.2@6272.96,1019.19 ; R88.1@6473.93,1230.39 6507.69,1230.39 v2(6526.08,1248.78) ; C134.2@6704.69,970.04 C148.1@6762.57,970.04 ; v2(6758.07,972.43) C148.1@6759.32,972.43 ; C148.1@6763.82,970.04 6793.77,999.99 6811.72,999.99 6811.72,1019.19 U20.2@6833.1,1019.19 ; U20.6@7193.33,1069.19 7197.7,1069.19 7216.9,1088.39 7232.66,1088.39 7250.7,1106.43 7250.7,1107.67 C100.1@7264.56,1107.67 7325.17,1107.67 C99.1@7325.36,1107.86 ; v2(7261.64,973.97) 7265.56,970.05 7318.02,970.05 7353.87,1005.9 7353.87,1019.19 U22.2@7393.24,1019.19 ; R104.1@7489.53,1239.92 7510.15,1239.92 v2(7541.79,1271.57) ; U22.6@7753.47,1069.19 7754.66,1068.01 v2(7793.14,1068.01) 7820.09,1068.01 C138.2@7835.13,1083.04 ; v2(7931.57,2426.24) 7989.92,2426.24 8052.15,2364.01 R92.1@8052.15,2362.05 ; C133.1@8200.2,2144.46 8210.57,2134.08 U16.6@8210.57,2073.57 ; U21.2@8258.53,2837.77 8258.53,2781.45 C160.1@8267.78,2772.2 ; C150.1@8274.16,2201.68 8260.57,2215.27 U18.2@8260.57,2275.9 8260.57,2305.57 v2(8308.53,2353.53)
  other v1: 4351.39,1560.24 5512.77,2865.37 5512.89,2942.75 4426.52,3113.34
  other v2: 6756.85,863.99 7287.17,863.99 5624.48,1150.7 7745.47,1256.56 6660.5,1281.77 6220.98,2522.94 6280.28,2522.94 6339.58,2522.94 7937.96,2522.98
  other v3: 5327.5,1378.82 5370.81,1378.82 5414.11,1378.82 5500.73,1378.82 5544.04,1378.82 5327.5,1422.12 5370.81,1422.12 5414.11,1422.12 5457.42,1422.12 5500.73,1422.12 5544.04,1422.12 5587.34,1422.12 5284.19,1465.43 5327.5,1465.43 5370.81,1465.43 5414.11,1465.43 5457.42,1465.43 5500.73,1465.43 5544.04,1465.43 5587.34,1465.43 5284.19,1508.74 5327.5,1508.74 5370.81,1508.74 5414.11,1508.74 5457.42,1508.74 5500.73,1508.74 5544.04,1508.74 5587.34,1508.74 5327.5,1552.04 5370.81,1552.04 5414.11,1552.04 5457.42,1552.04 5500.73,1552.04 5544.04,1552.04 5587.34,1552.04 5327.5,1595.35 5370.81,1595.35 5414.11,1595.35 5457.42,1595.35 5905.73,1843.63 5951,1843.63 5860.45,1888.91 5905.73,1888.91 5951,1888.91 5860.45,1934.18 5905.73,1934.18 5951,1934.18 5860.45,1979.46 5905.73,1979.46 5951,1979.46 5905.73,2024.73 5084.64,2126.3 5129.91,2126.3 5175.19,2126.3 5039.36,2171.57 5084.64,2171.57 5129.91,2171.57 5175.19,2171.57 5220.47,2171.57 5039.36,2216.85 5084.64,2216.85 5129.91,2216.85 5175.19,2216.85 5220.47,2216.85 5583.31,2444.29 5628.59,2444.29 5673.86,2444.29 5719.14,2444.29 5583.31,2489.56 5628.59,2489.56 5673.86,2489.56 5719.14,2489.56 5764.42,2489.56 5583.31,2534.84 5628.59,2534.84 5673.86,2534.84 5719.14,2534.84 5764.42,2534.84
  other v4: 4360.01,4053.34 4418.51,4053.34 4477.32,4053.83 4360.01,4118.47 4418.51,4118.47 4477.32,4118.96 4360.01,4183.61 4418.51,4183.61 4477.32,4184.1 4360.01,4248.74 4418.51,4248.74 4477.32,4249.23
  other v5: 8372.64,1356.91 4984.91,2441.99 5078,2590.66
Load_good: Q50.3 R63.1 U1.27 | length 1783.5
  Top Layer w10: Q50.3@5936.39,2754.92 6389.33,2754.92 6436.75,2802.34 6512.36,2802.34 6512.49,2802.2 6602.07,2802.2 6627.75,2776.53 v1(6675.71,2776.53) ; v6(7276.8,3435.75) U1.27@7307.26,3435.75
  Top Layer w20: R63.1@5920.67,2818.1 5928.36,2810.41 Q50.3@5928.36,2746.9
  Bottom Layer w10: v1(6675.71,2776.53) 6674.77,2777.46 6674.77,2827.63 7275.65,3428.51 7275.65,3434.6 v6(7276.8,3435.75)
LoadCurr+: Rshunt1.3 U9.8 | length 394.4
  Bottom Layer w20: Rshunt1.3@4231.99,2860.57 4231.99,2963.9 4243.71,2975.62 4364.02,2975.62 4375.74,2963.9 U9.8@4375.74,2826.26
LoadCurr-: Rshunt1.4 U9.1 | length 417.9
  Bottom Layer w20: Rshunt1.4@4231.99,3102.57 4231.99,3018.57 4246.36,3004.2 4362.21,3004.2 4373.93,3015.92 4373.93,3194.53 U9.1@4375.74,3196.34
"Net12V Supply_1": "12V Supply.1" "Supply Sel.3" TP1.1 | length 658.2
  Top Layer w20: 4920.66,967.72 5209.17,967.72 5303.52,873.38 5303.52,648.22 5311.39,640.35
NetC3_1: C3.1 U1.45 Y1.2 | length 280.9
  Top Layer w10: v1(7462.85,3170.91) 7462.85,3173.45 7490.33,3200.92 U1.45@7490.33,3226.18
  Bottom Layer w10: C3.1@7404.53,3003.42 7404.53,3097.39 Y1.2@7394.73,3107.19 7411.39,3123.84 7411.39,3144.12 7417.25,3149.98 7441.93,3149.98 v1(7462.85,3170.91)
NetC4_1: C4.1 U1.46 Y1.1 | length 244.7
  Top Layer w10: v1(7507.63,3174.46) 7507.63,3177.17 7510.01,3179.55 U1.46@7510.01,3232.99
  Bottom Layer w10: C4.1@7473.54,3003.42 7473.54,3057.49 7478.63,3062.59 7478.63,3092.66 Y1.1@7493.16,3107.19 7493.16,3159.59 7507.63,3174.06 v1(7507.63,3174.46)
NetC9_1: C9.1 C10.2 C12.2 C20.2 C23.2 J_LS.1 U3.13 U3.14 U3.15 U3.16 | length 270.9
  Top Layer w20: C10.2@5019.89,1689.95 5020.42,1689.42 5100.58,1689.42 C20.2@5101.11,1688.89 5103.09,1686.91 5172.36,1686.91 C12.2@5174.34,1684.93 ; U3.13@5410.77,1750.58 5410.77,1819.28 5438.48,1846.99 C9.1@5438.48,1853.49
  other v7: 5236.28,1808.23 5279.94,1808.23 5323.6,1808.23 5367.26,1808.23
NetC9_2: C9.2 U3.12 | length 126.8
  Top Layer w20: U3.12@5460.77,1750.58 5460.77,1767.58 5503.48,1810.3 5503.48,1838.49 C9.2@5518.48,1853.49
NetC11_1: C11.1 C19.1 J_5V.1 R13.2 U4.6 U4.7 U4.8 | length 510.6
  Top Layer w20: U4.6@6135.65,1834.18 U4.7@6135.65,1884.18 U4.8@6135.65,1934.18 6136.48,1935.01 6246.03,1935.01 C19.1@6250.36,1939.35 6255.88,1944.86 v1(6327.34,1944.86)
  Bottom Layer w20: R13.2@6123.24,1919.82 6126.09,1922.66 6210.54,1922.66 C11.1@6213.39,1925.51 6307.99,1925.51 v1(6327.34,1944.86)
NetC11_2: C11.2 R13.1 R16.2 U4.9 | length 363.1
  Top Layer w20: v1(6055.04,1985.02) 6055.88,1984.18 U4.9@6135.65,1984.18
  Bottom Layer w20: v1(6055.04,1985.02) 6108.45,1985.02 R13.1@6123.24,1999.82 ; R16.2@6141.04,2103.8 6141.04,2014.82 6126.04,1999.82 R13.1@6123.24,1999.82 ; C11.2@6213.39,1988.5 6207.73,1994.16 6128.9,1994.16 R13.1@6123.24,1999.82
NetC15_1: "Supply Sel.1" C15.1 C18.2 R12.2 U5.3 | length 589.5
  Bottom Layer w20: C15.1@4458.07,1175.27 4458.07,1177.28 4520.66,1239.87 R12.2@4520.66,1241.88 4561.19,1282.41 4591.82,1282.41 U5.3@4596.26,1286.85 4669.64,1286.85 4681.3,1298.51 C18.2@4786.35,1298.51 4822.77,1298.51 4903.1,1218.19 4903.1,1185.28 4920.66,1167.72
NetC25_1: C25.1 C27.1 J_1V85.2 R11.2 U6.6 U6.7 U6.8 | length 291.9
  Top Layer w20: U6.8@5673.86,2719.49 C25.1@5673.86,2792.17 ; R11.2@5676.62,3018.04 5680.62,3014.05 5680.62,2906.68 C27.1@5684.61,2902.69 5684.75,2902.55 5684.75,2802.34 C25.1@5684.88,2802.2
NetC25_2: C25.2 R11.1 R19.2 U6.9 | length 561.3
  Top Layer w20: R11.1@5596.62,3018.04 5494.81,3018.04 5473.45,2996.68 5473.45,2803.05 R19.2@5478.31,2798.19 5480.32,2800.2 5619.89,2800.2 C25.2@5621.89,2802.2 5621.89,2738.59 5623.86,2736.61 U6.9@5623.86,2719.49
NetC28_1: C28.1 D9.2 R119.2 | length 204.3
  Top Layer w20: D9.2@5467.27,3448.58 5474.58,3455.9 5579.62,3455.9 R119.2@5586.93,3463.21 C28.1@5586.93,3384.61
NetC29_1: C29.1 D9.1 D10.2 R22.2 | length 596.1
  Top Layer w20: R22.2@5213.78,3751.17 5213.78,3693.77 5178.86,3658.84 5172.86,3658.84 5164.85,3650.83 D10.2@5164.85,3644.83 5164.85,3638.82 5172.86,3630.81 5191.31,3630.81 5274.28,3547.85 C29.1@5274.28,3526.19 5274.28,3504.54 5285.93,3492.88 5288.03,3492.88 5461.27,3319.65 D9.1@5467.27,3319.65
NetC29_2: C29.2 C125.2 J_PWM.2 | length 314.4
  Top Layer w20: C29.2@5404.2,3526.19 5404.2,3547.85 5419.32,3562.96 C125.2@5419.32,3693.5 5502.42,3693.5 5536.51,3659.4 J_PWM.2@5546.01,3659.4
NetC33_1: C33.1 C128.1 J_3V3.1 R20.2 U26.6 U26.7 U26.8
NetC33_2: C33.2 R20.1 R23.2 U26.9 | length 440.2
  Top Layer w20: U26.9@5079.91,2401.49 5079.91,2480.49 5053.36,2507.04 R23.2@5053.36,2513.54 ; R20.1@5121.8,2677.27 5121.8,2672.97 5106.8,2657.97 5082.17,2657.97 5038.36,2614.16 5038.36,2528.54 R23.2@5053.36,2513.54 ; C33.2@5141.16,2488.45 5140.18,2488.45 5115.09,2513.54 5060.57,2513.54 R23.2@5053.36,2513.54
NetC35_1: C35.1 U9.3 U9.4 | length 174
  Bottom Layer w20: C35.1@4474.01,3319.65 4474.87,3318.78 4474.87,3197.21 U9.3@4475.74,3196.34 U9.4@4525.74,3196.34
NetC36_1: C36.1 U11.3 U11.4 | length 162.6
  Top Layer w20: U11.3@4212.43,996.66 U11.4@4262.43,996.66 4260.61,994.85 4260.61,888.16 C36.1@4258.22,885.77
NetC51_1: C51.1 Q38.1 Q44.3 R50.2 R53.1 | length 487.9
  Top Layer w20: R53.1@4698.38,3094.01 4704.88,3094.01 4744.01,3054.87 4786.43,3054.87 C51.1@4801.43,3039.87 ; C51.1@4801.61,3039.7 C51.1@4808.11,3039.7 ; Q44.3@4839.75,2877.01 4839.75,2878.07 4840.5,2878.82 4870.04,2878.82 4898.68,2907.46 4905.75,2914.53 4905.75,2934.1 R50.2@4920.75,2949.1 4920.75,2955.6 4877.47,2998.89 4842.42,2998.89 4822.93,3018.37 4822.93,3024.87 C51.1@4808.11,3039.7 ; Q38.1@4883.25,3039.52 4883.08,3039.7 C51.1@4808.11,3039.7
NetC52_1: C52.1 Q39.1 R52.1 U10.1 | length 284.8
  Top Layer w20: Q39.1@4371.06,1606.25 4371.81,1605.51 4469.46,1605.51 C52.1@4478.99,1595.98 R52.1@4478.99,1511.8 4474.62,1516.18 U10.1@4392.32,1516.18
NetC53_1: C53.1 Q48.1 R56.1 U12.1 | length 597.7
  Top Layer w20: Q48.1@4389.84,1936.76 4480.44,1936.76 4492.8,1924.4 4589.15,1924.4 C53.1@4604.15,1909.4 4619.15,1924.4 4662.94,1924.4 4813.06,2074.52 R56.1@4813.06,2081.02 4813.06,2144.07 U12.1@4830.89,2161.89
NetC84_1: C84.1 R82.2 R83.1 TP7.1 U15.1 | length 719
  Top Layer w14: R83.1@7246.8,2514.2 7247.72,2513.29 7301.94,2513.29 v2(7302.86,2512.37) ; R82.2@7419.18,2039.77 7419.18,2129.96 C84.1@7419.45,2130.24 7419.45,2136.74 7437.45,2154.74 7439.54,2154.74 7492.08,2207.27 7492.08,2267.54 7488.75,2270.87 7476.18,2270.87 7457.92,2289.13 v2(7455.28,2289.13)
  Top Layer w16: v2(7302.86,2512.37) 7303.76,2511.47 7372.14,2511.47 TP7.1@7373.04,2510.57
  Analog Signal w14: v2(7302.86,2512.37) 7455.28,2359.95 v2(7455.28,2289.13)
NetC84_2: C84.2 R82.1 R85.2 R109.2 TP26.1 U15.2 | length 949.3
  Top Layer w14: v2(7502.48,1964.23) 7502.48,2036.46 R82.1@7499.18,2039.77 7499.18,2129.96 7510.96,2141.74 7510.96,2174.53 7542.08,2205.65 U15.2@7542.08,2237.41
  Analog Signal w20: v2(7502.48,1964.23) 7645.1,1964.23 7789.76,1819.57 7793.33,1819.57 v2(7859.57,1753.33)
  Bottom Layer w20: v2(7859.57,1753.33) 7954.26,1753.33 R109.2@7972.15,1771.22 7972.15,1679.11 R85.2@7971.84,1678.79
NetC85_1: C85.1 R84.2 R86.1 TP12.1 U19.14 | length 1057.9
  Top Layer w14: R84.2@6387.74,1550.96 6480.77,1550.96 C85.1@6481.86,1552.05 6495.07,1565.26 U19.14@6604.71,1565.26 6605.98,1566.54 6674.83,1566.54 v2(6676.13,1567.83) ; v2(6991.66,2001.17) 7034.61,2044.12 R86.1@7034.61,2106.31
  Top Layer w16: TP12.1@6930.6,2003.81 TP12.1@6928.03,2003.81 6929.35,2002.49 6990.34,2002.49 v2(6991.66,2001.17)
  Analog Signal w14: v2(6676.13,1567.83) 6676.13,1699.71 6829.78,1853.36 6843.85,1853.36 v2(6991.66,2001.17)
NetC85_2: C85.2 R84.1 R87.2 R88.2 TP27.1 U19.13 | length 856.1
  Top Layer w14: v2(6306.15,1630.96) R84.1@6387.74,1630.96 6388.82,1632.05 C85.2@6481.86,1632.05 6498.64,1615.26 U19.13@6604.71,1615.26
  Top Layer w20: TP27.1@6304.69,1416.66 6377.56,1416.66 6388.89,1405.33 v2(6389.97,1405.33)
  Analog Signal w14: v2(6306.15,1630.96) 6306.15,1489.14 v2(6389.97,1405.33)
  Bottom Layer w20: v2(6389.97,1405.33) 6389.97,1325.15 R87.2@6375.2,1310.39 R88.2@6473.93,1310.39
NetC92_1: C92.1 R90.2 R91.1 TP13.1 U15.7 | length 1063.3
  Top Layer w14: R91.1@7246.8,2659.55 7247.87,2658.48 7300.88,2658.48 v2(7301.94,2657.42) ; v2(7791.44,2310.31) 7791.76,2309.99 7791.76,2237.72 U15.7@7792.08,2237.41 7792.08,2207.27 7818.33,2181.03 7838.61,2181.03 7881.59,2138.05 R90.2@7881.59,2131.55 7881.59,2044.16 C92.1@7881.24,2043.81
  Top Layer w16: v2(7301.94,2657.42) 7339.04,2694.52 TP13.1@7339.04,2700.2
  Analog Signal w14: v2(7301.94,2657.42) 7350.7,2657.42 7697.81,2310.31 v2(7791.44,2310.31)
NetC92_2: C92.2 R89.2 R90.1 R92.2 TP28.1 U15.6 | length 843.4
  Top Layer w14: U15.6@7742.08,2237.41 7742.08,2207.27 7783.59,2165.77 7783.59,2149.55 R90.1@7801.59,2131.55 7801.59,2044.16 C92.2@7801.24,2043.81 7797.93,2040.5 v2(7797.93,1971.31)
  Top Layer w20: TP28.1@7870.26,2227.19 7907.28,2264.22 7913.85,2264.22 v2(7914.62,2264.98)
  Analog Signal w14: v2(7797.93,1971.31) 7914.62,2088 v2(7914.62,2264.98)
  Bottom Layer w16: v2(7914.62,2264.98) R89.2@7972.7,2264.98
  Bottom Layer w20: R92.2@7972.15,2362.05 7972.7,2361.5 R89.2@7972.7,2271.2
